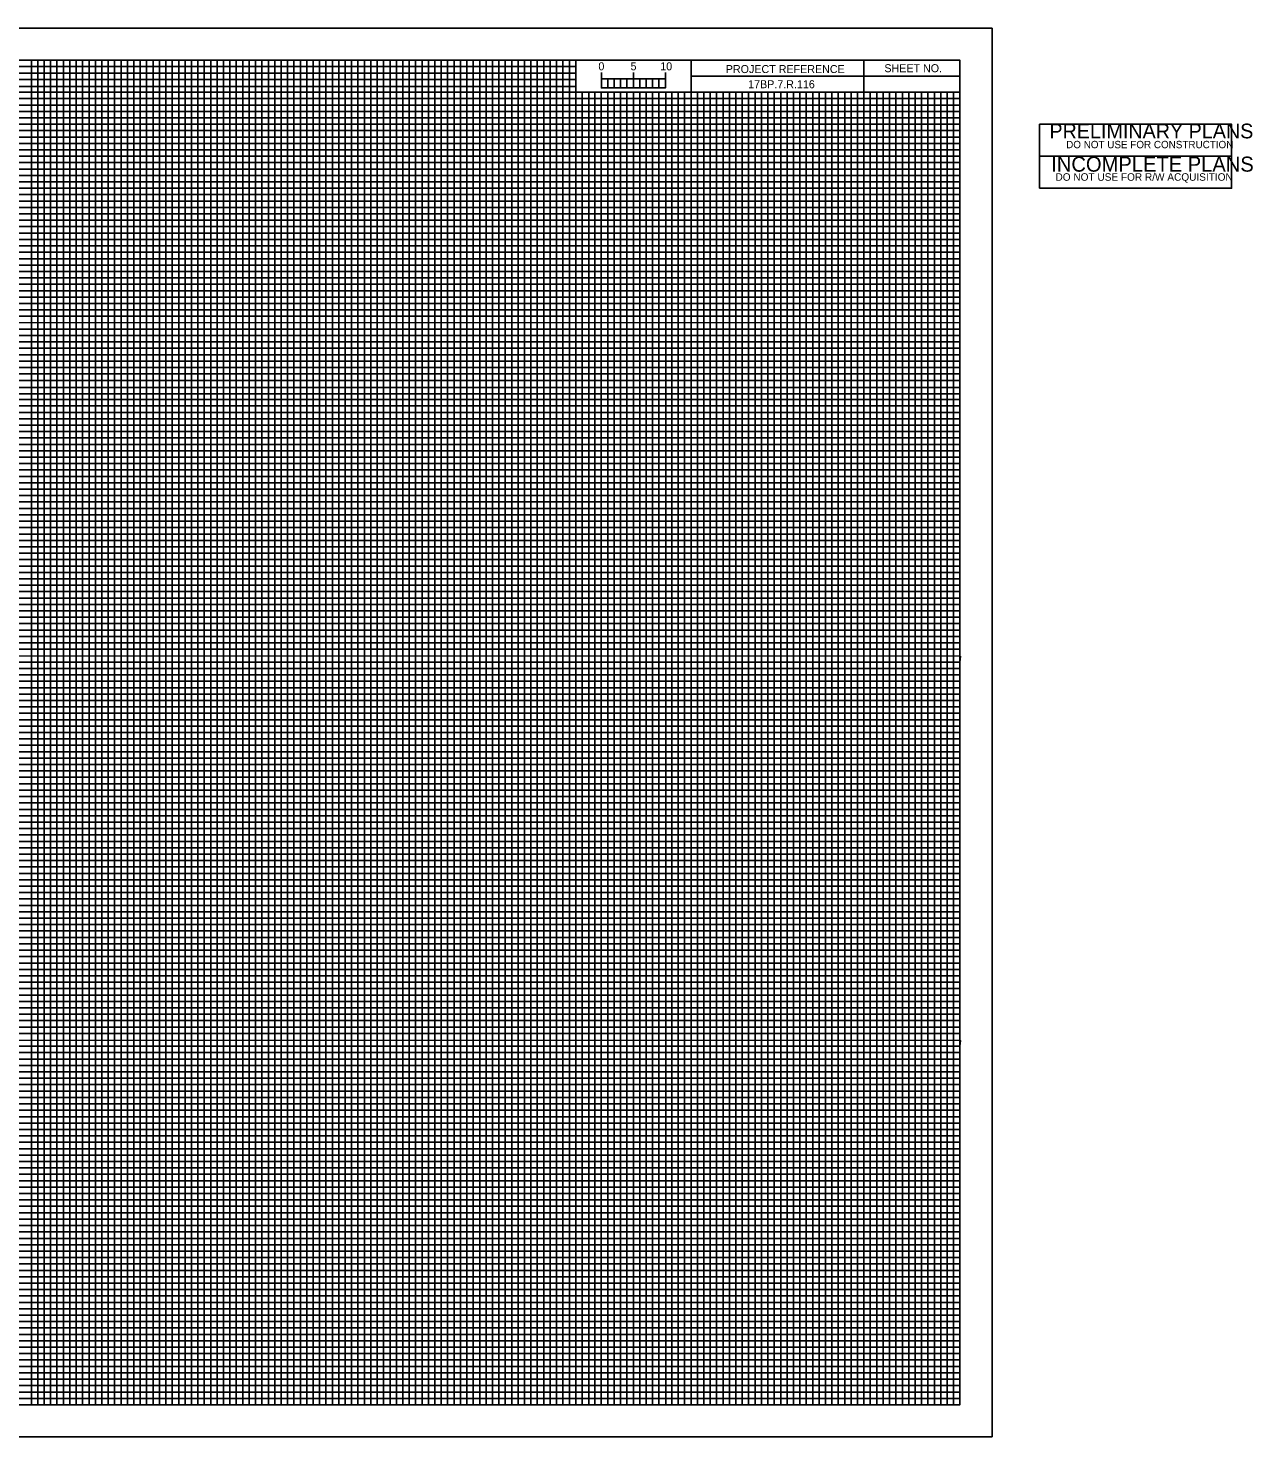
# Model space of a CAD drawing. Extents: x -1.5 to 36.6, y -0.5 to 21.5.
# Drawn here: x 17.45 to 36.57, y -0.5 to 21.5 of the extents above; entities that cross this region are included whole.
import ezdxf

# ---------------------------------------------------------------- set-up
doc = ezdxf.new("R2010")
doc.units = 0
for name, color, linetype in [('Old_Level_1', 7, 'Continuous'), ('Old_Level_18', 7, 'Continuous'), ('Old_Level_24', 7, 'Continuous'), ('Old_Level_38', 7, 'Continuous'), ('Old_Level_40', 7, 'Continuous'), ('Old_Level_41', 7, 'Continuous'), ('Old_Level_42', 7, 'Continuous'), ('Old_Level_43', 7, 'Continuous'), ('Old_Level_44', 7, 'Continuous'), ('Old_Level_62', 7, 'Continuous'), ('Old_Level_63', 7, 'Continuous')]:
    doc.layers.add(name, color=color, linetype=linetype)

msp = doc.modelspace()

# ---------------------------------------------------------------- linework, layer by layer
at = {"layer": 'Old_Level_1'}
msp.add_lwpolyline([(33.242, 19), (33.242, 19.5), (36.242, 19.5), (36.242, 19)], close=True, dxfattribs=at)
at = {"layer": 'Old_Level_18'}
msp.add_lwpolyline([(32, 21), (0, 21), (0, 0), (32, 0)], close=True, dxfattribs=at)
at = {"layer": 'Old_Level_24'}
msp.add_lwpolyline([(33.242, 20), (36.242, 20), (36.242, 19.5), (33.242, 19.5)], close=True, dxfattribs=at)
at = {"layer": 'Old_Level_38'}
for p, q in [((26.4, 20.567), (26.4, 20.808)), ((26.4, 20.708), (26.4, 20.808)), ((26.9, 20.567), (26.9, 20.808)), ((27.4, 20.567), (27.4, 20.808)), ((27.4, 20.708), (27.4, 20.808))]:
    msp.add_line(p, q, dxfattribs=at)
for points in [[(27.4, 20.708), (26.4, 20.708), (26.4, 20.567), (27.4, 20.567)], [(26.4, 20.708), (26.5, 20.708), (26.5, 20.567), (26.4, 20.567)], [(26.6, 20.708), (26.7, 20.708), (26.7, 20.567), (26.6, 20.567)], [(26.8, 20.708), (26.9, 20.708), (26.9, 20.567), (26.8, 20.567)], [(27, 20.708), (27.1, 20.708), (27.1, 20.567), (27, 20.567)], [(27.2, 20.708), (27.3, 20.708), (27.3, 20.567), (27.2, 20.567)]]:
    msp.add_lwpolyline(points, close=True, dxfattribs=at)
at = {"layer": 'Old_Level_40'}
for p, q in [((30.5, 20.5), (30.5, 21)), ((30.5, 21), (30.5, 20.5)), ((27.8, 20.749), (27.8, 20.499)), ((32, 20.749), (27.8, 20.749)), ((32, 20.749), (28, 20.749)), ((26, 20.5), (32, 20.5))]:
    msp.add_line(p, q, dxfattribs=at)
for points in [[(27.8, 21), (26, 21), (26, 20.5), (27.8, 20.5)], [(32, 21), (27.8, 21), (27.8, 20.5), (32, 20.5)]]:
    msp.add_lwpolyline(points, close=True, dxfattribs=at)
at = {"layer": 'Old_Level_41'}
for p, q in [((19, 21), (18, 21)), ((18, 21), (18, 0)), ((19, 0), (19, 21)), ((21, 21), (20, 21)), ((20, 21), (20, 0)), ((21, 0), (21, 21)), ((23, 21), (22, 21)), ((22, 21), (22, 0)), ((23, 0), (23, 21)), ((25, 21), (24, 21)), ((24, 21), (24, 0)), ((25, 0), (25, 21)), ((26, 21), (26, 20.503)), ((26, 20.5), (26, 0)), ((27, 0), (27, 20.5)), ((28, 20.5), (28, 0)), ((29, 0), (29, 20.5)), ((30, 20.5), (30, 0)), ((31, 0), (31, 20.5)), ((18, 0), (17, 0)), ((20, 0), (19, 0)), ((22, 0), (21, 0)), ((24, 0), (23, 0)), ((26, 0), (25, 0)), ((28, 0), (27, 0)), ((30, 0), (29, 0)), ((32, 0), (31, 0)), ((32, 0), (32, 0))]:
    msp.add_line(p, q, dxfattribs=at)
for points in [[(0, 20), (32, 20), (32, 19), (0, 19)], [(0, 18), (32, 18), (32, 17), (0, 17)], [(0, 16), (32, 16), (32, 15), (0, 15)], [(0, 14), (32, 14), (32, 13), (0, 13)], [(0, 12), (32, 12), (32, 11), (0, 11)], [(0, 10), (32, 10), (32, 9), (0, 9)], [(0, 8), (32, 8), (32, 7), (0, 7)], [(0, 6), (32, 6), (32, 5), (0, 5)], [(0, 4), (32, 4), (32, 3), (0, 3)], [(0, 2), (32, 2), (32, 1), (0, 1)]]:
    msp.add_lwpolyline(points, dxfattribs=at)
at = {"layer": 'Old_Level_42'}
for points in [[(16.5, 0), (17.5, 0), (17.5, 21), (18.5, 21), (18.5, 0), (19.5, 0), (19.5, 21), (20.5, 21), (20.5, 0), (21.5, 0), (21.5, 21), (22.5, 21), (22.5, 0), (23.5, 0), (23.5, 21), (24.5, 21), (24.5, 0), (25.5, 0), (25.5, 21), (25.993, 21), (26, 21), (26, 20.503)], [(0, 20.5), (26, 20.5)], [(26, 20.503), (26, 20.5)], [(26.499, 20.5), (26.499, 0), (27.5, 0), (27.5, 20.5)], [(28.5, 20.5), (28.5, 0), (29.5, 0), (29.5, 20.5)], [(30.5, 20.5), (30.5, 0), (31.5, 0), (31.5, 20.5)], [(0, 18.5), (32, 18.5), (32, 19.5), (0, 19.5)], [(0, 16.5), (32, 16.5), (32, 17.5), (0, 17.5)], [(0, 14.5), (32, 14.5), (32, 15.5), (0, 15.5)], [(0, 12.5), (32, 12.5), (32, 13.5), (0, 13.5)], [(0, 10.5), (32, 10.5), (32, 11.5), (0, 11.5)], [(0, 8.5), (32, 8.5), (32, 9.5), (0, 9.5)], [(0, 6.5), (32, 6.5), (32, 7.5), (0, 7.5)], [(0, 4.5), (32, 4.5), (32, 5.5), (0, 5.5)], [(0, 2.5), (32, 2.5), (32, 3.5), (0, 3.5)], [(0, 0.5), (32, 0.5), (32, 1.5), (0, 1.5)]]:
    msp.add_lwpolyline(points, dxfattribs=at)
at = {"layer": 'Old_Level_43'}
for p, q in [((0, 20.9), (26, 20.9)), ((26, 20.798), (0, 20.798)), ((0, 20.7), (26, 20.7)), ((26, 20.9), (26, 20.798)), ((26, 20.7), (26, 20.589)), ((26, 20.589), (0, 20.589)), ((26.601, 20.5), (26.601, 0)), ((26.7, 0), (26.7, 20.5)), ((26.8, 20.5), (26.8, 0)), ((26.9, 0), (26.9, 20.5)), ((0, 20.4), (32, 20.4)), ((26.601, 0), (26.5, 0)), ((26.8, 0), (26.7, 0))]:
    msp.add_line(p, q, dxfattribs=at)
for points in [[(0, 20.3), (32, 20.3)], [(32, 20.25), (32, 20.2), (0, 20.2)], [(0, 20.1), (32, 20.1), (32, 19.9), (0, 19.9)], [(0, 19.8), (32, 19.8), (32, 19.7), (0, 19.698)], [(0, 19.6), (32, 19.6), (32, 19.4), (0, 19.4)], [(0, 19.3), (32, 19.3), (32, 19.2), (0, 19.2)], [(0, 19.1), (32, 19.1), (32, 18.9), (0, 18.9)], [(0, 18.8), (32, 18.8), (32, 18.7), (0, 18.7)], [(0, 18.6), (32, 18.6), (32, 18.4), (0, 18.4)], [(0, 18.3), (32, 18.3), (32, 18.2), (0, 18.2)], [(0, 18.1), (32, 18.1), (32, 17.9), (0, 17.9)], [(0, 17.8), (32, 17.8), (32, 17.7), (0, 17.7)], [(0, 17.6), (32, 17.6), (32, 17.395), (32, 17.3), (32, 17.2), (0, 17.2)], [(0, 17.4), (32, 17.4), (32, 17.3), (0, 17.3)], [(0, 17.1), (32, 17.1), (32, 16.9), (0, 16.903)], [(0, 16.903), (32, 16.9), (32, 16.8), (0, 16.8)], [(0, 16.7), (32, 16.7), (32, 16.6), (0, 16.6)], [(0, 16.4), (32, 16.4), (32, 16.3), (0, 16.3)], [(0, 16.2), (32, 16.2), (32, 16.1), (0, 16.1)], [(-0.007, 15.889), (32, 15.889), (32, 15.788), (-0.007, 15.788)], [(0, 15.7), (32, 15.7), (32, 15.6), (0, 15.6)], [(0, 15.4), (32, 15.4), (32, 15.3), (0, 15.3)], [(0, 15.2), (32, 15.2), (32, 15.1), (0, 15.1)], [(0, 14.9), (32, 14.9), (32, 14.8), (0, 14.8)], [(0, 14.7), (32, 14.7), (32, 14.6), (0, 14.6)], [(0, 14.4), (32, 14.4), (32, 14.3), (0, 14.3)], [(0, 14.2), (32, 14.2), (32, 14.1), (0, 14.1)], [(0, 13.9), (32, 13.9), (31.999, 13.798), (0, 13.8)], [(0, 13.7), (32, 13.7), (32, 13.6), (0, 13.6)], [(0, 13.4), (32, 13.4), (32, 13.3), (0, 13.3)], [(0, 13.2), (32, 13.2), (32, 13.1), (0, 13.1)], [(0, 12.9), (32, 12.9), (32, 12.8), (0, 12.8)], [(0, 12.7), (32, 12.7), (32, 12.6), (0, 12.6)], [(0, 12.4), (32, 12.4), (32, 12.3), (0, 12.3)], [(0, 12.2), (32, 12.2), (32, 12.1), (0, 12.1)], [(0, 11.9), (32, 11.9), (32, 11.8), (0, 11.8)], [(0, 11.699), (32.007, 11.691), (32, 11.6), (0, 11.6)], [(0, 11.4), (32, 11.4), (32, 11.3), (0, 11.3)], [(0, 11.2), (32, 11.2), (32, 11.1), (0, 11.1)], [(0, 10.9), (32, 10.9), (32, 10.8), (0, 10.8)], [(0, 10.7), (32, 10.7), (32, 10.6), (0, 10.6)], [(0, 10.4), (32, 10.4), (32, 10.3), (0, 10.3)], [(0, 10.2), (32, 10.2), (32, 10.1), (0, 10.1)], [(0, 9.9), (32, 9.9), (32, 9.8), (0, 9.8)], [(0, 9.7), (32, 9.7), (32, 9.6), (0, 9.6)], [(0, 9.4), (32, 9.4), (32, 9.3), (0, 9.3)], [(0, 9.2), (32, 9.2), (32, 9.1), (0, 9.1)], [(0, 8.9), (32, 8.9), (32, 8.8), (0, 8.8)], [(0, 8.7), (32, 8.7), (32, 8.6), (0, 8.6)], [(0, 8.4), (32, 8.4), (32, 8.3), (0, 8.3)], [(0, 8.2), (32, 8.2), (32, 8.1), (0, 8.1)], [(0, 7.9), (32, 7.9), (31.999, 7.798), (0, 7.8)], [(0, 7.7), (32, 7.7), (32, 7.6), (0, 7.6)], [(0, 7.4), (32, 7.4), (32, 7.3), (0, 7.3)], [(0, 7.2), (32, 7.2), (32, 7.1), (0, 7.1)], [(0, 6.9), (32, 6.9), (32, 6.8), (0, 6.8)], [(0, 6.7), (32, 6.7), (32, 6.6), (0, 6.6)], [(0, 6.4), (32, 6.4), (32, 6.3), (0, 6.3)], [(0, 6.2), (32, 6.2), (32, 6.1), (0, 6.1)], [(0, 5.9), (32, 5.9), (32, 5.8), (0, 5.8)], [(0, 5.699), (32.007, 5.691), (32, 5.6), (0, 5.6)], [(0, 5.4), (32, 5.4), (32, 5.3), (0, 5.3)], [(0, 5.2), (32, 5.2), (32, 5.1), (0, 5.1)], [(0, 4.9), (32, 4.9), (32, 4.8), (0, 4.8)], [(0, 4.7), (32, 4.7), (32, 4.6), (0, 4.6)], [(0, 4.4), (32, 4.4), (32, 4.3), (0, 4.3)], [(0, 4.2), (32, 4.2), (32, 4.1), (0, 4.1)], [(0, 3.9), (32, 3.9), (32, 3.8), (0, 3.8)], [(0, 3.7), (32, 3.7), (32, 3.6), (0, 3.6)], [(0, 3.4), (32, 3.4), (32, 3.3), (0, 3.3)], [(0, 3.2), (32, 3.2), (32, 3.1), (0, 3.1)], [(0, 2.9), (32, 2.9), (32, 2.8), (0, 2.8)], [(0, 2.7), (32, 2.7), (32, 2.6), (0, 2.6)], [(0, 2.4), (32, 2.4), (32, 2.3), (0, 2.3)], [(0, 2.2), (32, 2.2), (32, 2.1), (0, 2.1)], [(0, 1.9), (32, 1.9), (32, 1.8), (0, 1.8)], [(0, 1.7), (32, 1.7), (32, 1.6), (0, 1.6)], [(0, 1.4), (32, 1.4), (32, 1.3), (0, 1.3)], [(0, 1.2), (32, 1.2), (32, 1.1), (0, 1.1)], [(0, 0.9), (32, 0.9), (32, 0.8), (0, 0.8)], [(0, 0.7), (32, 0.7), (32, 0.6), (0, 0.6)], [(0, 0.4), (32, 0.4), (32, 0.3), (0, 0.3)], [(0, 0.2), (32, 0.2), (32, 0.1), (0, 0.1)]]:
    msp.add_lwpolyline(points, dxfattribs=at)
at = {"layer": 'Old_Level_44'}
for points in [[(17.5, 0), (17.6, 0), (17.6, 21), (17.7, 21), (17.7, 0)], [(17.7, 0), (17.8, 0), (17.8, 21), (17.9, 21), (17.9, 0)], [(18, 0), (18.1, 0), (18.1, 21), (18.2, 21), (18.2, 0)], [(18.2, 0), (18.3, 0), (18.3, 21), (18.4, 21), (18.4, 0)], [(18.5, 0), (18.6, 0), (18.6, 21), (18.7, 21), (18.7, 0)], [(18.7, 0), (18.8, 0), (18.8, 21), (18.9, 21), (18.9, 0)], [(19, 0), (19.1, 0), (19.1, 21), (19.2, 21), (19.2, 0)], [(19.2, 0), (19.3, 0), (19.3, 21), (19.4, 21), (19.4, 0)], [(19.5, 0), (19.6, 0), (19.6, 21), (19.7, 21), (19.7, 0)], [(19.7, 0), (19.8, 0), (19.8, 21), (19.9, 21), (19.9, 0)], [(20, 0), (20.1, 0), (20.1, 21), (20.2, 21), (20.2, 0)], [(20.2, 0), (20.3, 0), (20.3, 21), (20.4, 21), (20.4, 0)], [(20.5, 0), (20.6, 0), (20.6, 21), (20.7, 21), (20.7, 0)], [(20.7, 0), (20.8, 0), (20.8, 21), (20.9, 21), (20.9, 0)], [(21, 0), (21.1, 0), (21.1, 21), (21.2, 21), (21.2, 0)], [(21.2, 0), (21.3, 0), (21.3, 21), (21.4, 21), (21.4, 0)], [(21.5, 0), (21.6, 0), (21.6, 21), (21.7, 21), (21.7, 0)], [(21.7, 0), (21.8, 0), (21.8, 21), (21.9, 21), (21.9, 0)], [(22, 0), (22.1, 0), (22.1, 21), (22.2, 21), (22.2, 0)], [(22.2, 0), (22.3, 0), (22.3, 21), (22.4, 21), (22.4, 0)], [(22.5, 0), (22.6, 0), (22.6, 21), (22.7, 21), (22.7, 0)], [(22.7, 0), (22.8, 0), (22.8, 21), (22.9, 21), (22.9, 0)], [(23, 0), (23.1, 0), (23.1, 21), (23.2, 21), (23.2, 0)], [(23.2, 0), (23.3, 0), (23.3, 21), (23.4, 21), (23.4, 0)], [(23.5, 0), (23.6, 0), (23.6, 21), (23.7, 21), (23.7, 0)], [(23.7, 0), (23.8, 0), (23.8, 21), (23.9, 21), (23.9, 0)], [(24, 0), (24.1, 0), (24.1, 21), (24.2, 21), (24.2, 0)], [(24.2, 0), (24.3, 0), (24.3, 21), (24.4, 21), (24.4, 0)], [(24.5, 0), (24.6, 0), (24.6, 21), (24.7, 21), (24.7, 0)], [(24.7, 0), (24.8, 0), (24.8, 21), (24.9, 21), (24.9, 0)], [(25, 0), (25.1, 0), (25.1, 21), (25.2, 21), (25.2, 0)], [(25.2, 0), (25.3, 0), (25.3, 21), (25.4, 21), (25.4, 0)], [(25.5, 0), (25.6, 0), (25.6, 21), (25.7, 21), (25.7, 0)], [(25.7, 0), (25.8, 0), (25.8, 21), (25.9, 21), (25.9, 0)], [(26, 0), (26.1, 0), (26.1, 20.5)], [(26.2, 0), (26.3, 0), (26.3, 20.5)], [(26.202, 20.5), (26.202, 0)], [(26.399, 20.5), (26.399, 0)], [(27, 0), (27.098, 0), (27.098, 20.5)], [(27.2, 20.5), (27.2, 0)], [(27.2, 0), (27.3, 0), (27.3, 20.5)], [(27.405, 20.5), (27.405, 0)], [(27.5, 0), (27.6, 0), (27.6, 20.5)], [(27.7, 20.5), (27.7, 0)], [(27.7, 0), (27.8, 0), (27.8, 20.5)], [(27.9, 20.5), (27.9, 0)], [(28, 0), (28.1, 0), (28.1, 20.5)], [(28.2, 20.5), (28.2, 0)], [(28.2, 0), (28.3, 0), (28.3, 20.5)], [(28.4, 20.5), (28.4, 0)], [(28.5, 0), (28.6, 0), (28.6, 20.5)], [(28.7, 20.5), (28.7, 0)], [(28.7, 0), (28.8, 0), (28.8, 20.5)], [(28.9, 20.5), (28.9, 0)], [(29, 0), (29.1, 0), (29.1, 20.5)], [(29.2, 20.5), (29.2, 0)], [(29.2, 0), (29.3, 0), (29.3, 20.5)], [(29.4, 20.5), (29.4, 0)], [(29.5, 0), (29.6, 0), (29.6, 20.5)], [(29.7, 20.5), (29.7, 0)], [(29.7, 0), (29.8, 0), (29.8, 20.5)], [(29.9, 20.5), (29.9, 0)], [(30, 0), (30.1, 0), (30.1, 20.5)], [(30.2, 20.5), (30.2, 0)], [(30.2, 0), (30.3, 0), (30.3, 20.5)], [(30.4, 20.5), (30.4, 0)], [(30.5, 0), (30.6, 0), (30.6, 20.5)], [(30.7, 20.5), (30.7, 0)], [(30.7, 0), (30.8, 0), (30.8, 20.5)], [(30.9, 20.5), (30.9, 0)], [(31, 0), (31.1, 0), (31.1, 20.5)], [(31.2, 20.5), (31.2, 0)], [(31.2, 0), (31.3, 0), (31.3, 20.5)], [(31.4, 20.5), (31.4, 0)], [(31.5, 0), (31.6, 0), (31.6, 20.5)], [(31.7, 20.5), (31.7, 0)], [(31.7, 0), (31.8, 0), (31.8, 20.5)], [(31.9, 20.5), (31.9, 0)]]:
    msp.add_lwpolyline(points, dxfattribs=at)
at = {"layer": 'Old_Level_62'}
msp.add_lwpolyline([(-1, 21), (32, 21), (32, 0), (-1, 0)], close=True, dxfattribs=at)
at = {"layer": 'Old_Level_63'}
msp.add_lwpolyline([(-1.5, -0.5), (32.5, -0.5), (32.5, 21.5), (-1.5, 21.5)], close=True, dxfattribs=at)

# ---------------------------------------------------------------- texts
at = {"layer": 'Old_Level_1'}
for s, height, p in [('INCOMPLETE PLANS', 0.2351, (33.425, 19.259)), ('DO NOT USE FOR R/W ACQUISITION', 0.11755, (33.491, 19.117))]:
    msp.add_text(s, height=height, dxfattribs=at).set_placement(p)
at = {"layer": 'Old_Level_24'}
for s, height, p in [('PRELIMINARY PLANS', 0.2304, (33.396, 19.779)), ('DO NOT USE FOR CONSTRUCTION', 0.1152, (33.658, 19.625))]:
    msp.add_text(s, height=height, dxfattribs=at).set_placement(p)
at = {"layer": 'Old_Level_38'}
for s, p in [('0', (26.354, 20.842)), ('5', (26.856, 20.842)), ('10', (27.32, 20.842))]:
    msp.add_text(s, height=0.125, dxfattribs=at).set_placement(p)
at = {"layer": 'Old_Level_40'}
for s, p in [('PROJECT REFERENCE', (28.343, 20.799)), ('SHEET NO.', (30.819, 20.812)), ('17BP.7.R.116', (28.692, 20.562))]:
    msp.add_text(s, height=0.125, dxfattribs=at).set_placement(p)

doc.saveas('drawing.dxf')
